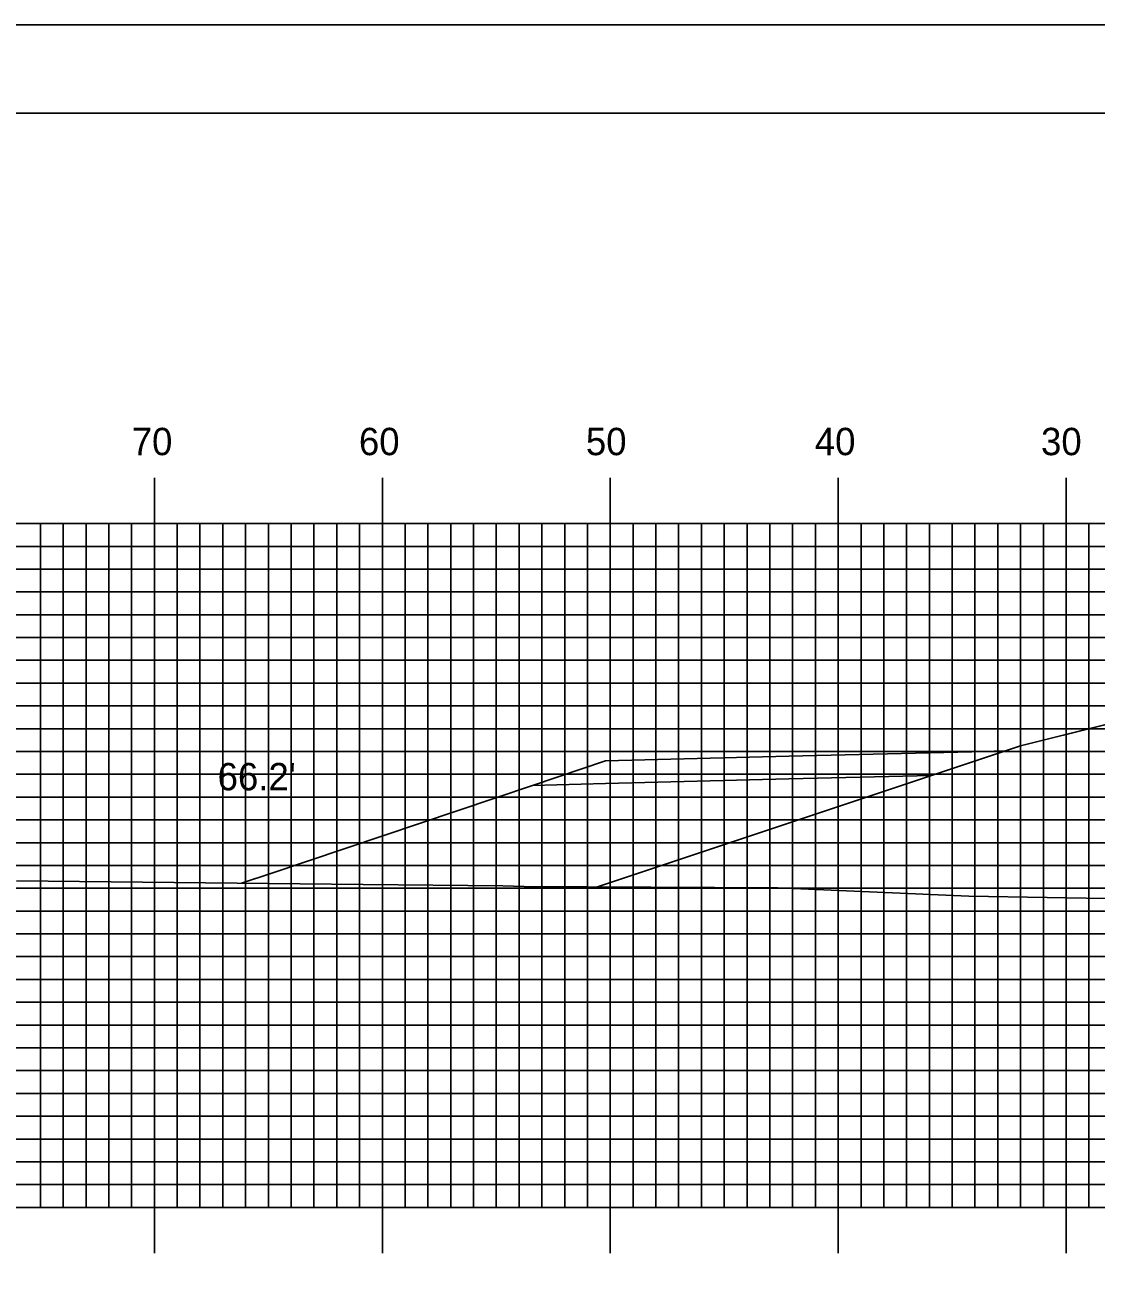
# Model space of a CAD drawing. Extents: x 1807832 to 1808175, y 442591 to 442811.
# Drawn here: x 1807922.1 to 1807969.1, y 442756.2 to 442810.5 of the extents above; entities that cross this region are included whole.
import ezdxf

# ---------------------------------------------------------------- set-up
doc = ezdxf.new("R2010")
doc.units = 0
for name, color, linetype in [('BORDER', 7, 'Continuous'), ('D_Roadway_Centerline', 7, 'Continuous'), ('D_Roadway_Drive_Gravel', 7, 'Continuous'), ('D_Roadway_SlopeLines', 7, 'Continuous'), ('D_Text_Standard', 7, 'Continuous'), ('H_V ANNOTATION', 7, 'Continuous'), ('MAJOR', 7, 'Continuous'), ('MINOR', 7, 'Continuous'), ('PLOT BOUNDARY', 7, 'Continuous'), ('S_Roadway_Centerline', 7, 'Continuous')]:
    doc.layers.add(name, color=color, linetype=linetype)

msp = doc.modelspace()

# ---------------------------------------------------------------- linework, layer by layer
at = {"layer": 'BORDER'}
msp.add_lwpolyline([(1807848.185, 442596.665), (1808168.185, 442596.665), (1808168.185, 442806.665), (1807848.185, 442806.665)], close=True, dxfattribs=at)
at = {"layer": 'D_Roadway_Centerline'}
msp.add_lwpolyline([(1807947.223, 442772.728), (1807965.785, 442778.915), (1807969.423, 442779.824), (1807977.785, 442781.915), (1807985.785, 442782.235), (1807997.785, 442782.475), (1808009.785, 442782.235), (1808017.785, 442781.915), (1808026.147, 442779.824), (1808029.785, 442778.915), (1808057.777, 442769.585)], dxfattribs=at)
at = {"layer": 'D_Roadway_Drive_Gravel'}
msp.add_lwpolyline([(1807963.65, 442778.658), (1807955.612, 442778.459), (1807947.575, 442778.261), (1807944.368, 442777.181), (1807947.575, 442777.261), (1807955.612, 442777.459), (1807961.883, 442777.614)], dxfattribs=at)
at = {"layer": 'D_Roadway_SlopeLines'}
for p, q in [((1807963.65, 442778.658), (1807965.123, 442778.694)), ((1807932.888, 442773.317), (1807931.61, 442772.887))]:
    msp.add_line(p, q, dxfattribs=at)
for points in [[(1807977.785, 442781.915), (1807965.785, 442778.915), (1807947.223, 442772.728)], [(1807947.575, 442778.261), (1807944.368, 442777.181), (1807932.888, 442773.317)]]:
    msp.add_lwpolyline(points, dxfattribs=at)
at = {"layer": 'MAJOR'}
for p, q in [((1807927.785, 442790.669), (1807927.785, 442788.665)), ((1807937.785, 442790.669), (1807937.785, 442788.665)), ((1807947.785, 442790.669), (1807947.785, 442788.665)), ((1807957.785, 442790.669), (1807957.785, 442788.665)), ((1807967.785, 442790.669), (1807967.785, 442788.665)), ((1807857.785, 442788.665), (1808137.785, 442788.665)), ((1807857.785, 442788.665), (1808137.785, 442788.665)), ((1807927.785, 442758.665), (1807927.785, 442788.665)), ((1807937.785, 442758.665), (1807937.785, 442788.665)), ((1807947.785, 442758.665), (1807947.785, 442788.665)), ((1807957.785, 442758.665), (1807957.785, 442788.665)), ((1807967.785, 442758.665), (1807967.785, 442788.665)), ((1807857.785, 442783.665), (1808137.785, 442783.665)), ((1807857.785, 442778.665), (1808137.785, 442778.665)), ((1807857.785, 442773.665), (1808137.785, 442773.665)), ((1807857.785, 442768.665), (1808137.785, 442768.665)), ((1807857.785, 442763.665), (1808137.785, 442763.665)), ((1807857.785, 442758.665), (1808137.785, 442758.665)), ((1807857.785, 442758.665), (1808137.785, 442758.665)), ((1807927.785, 442756.661), (1807927.785, 442758.665)), ((1807937.785, 442756.661), (1807937.785, 442758.665)), ((1807947.785, 442756.661), (1807947.785, 442758.665)), ((1807957.785, 442756.661), (1807957.785, 442758.665)), ((1807967.785, 442756.661), (1807967.785, 442758.665))]:
    msp.add_line(p, q, dxfattribs=at)
at = {"layer": 'MINOR'}
for p, q in [((1807922.785, 442758.665), (1807922.785, 442788.665)), ((1807923.785, 442758.665), (1807923.785, 442788.665)), ((1807924.785, 442758.665), (1807924.785, 442788.665)), ((1807925.785, 442758.665), (1807925.785, 442788.665)), ((1807926.785, 442758.665), (1807926.785, 442788.665)), ((1807928.785, 442758.665), (1807928.785, 442788.665)), ((1807929.785, 442758.665), (1807929.785, 442788.665)), ((1807930.785, 442758.665), (1807930.785, 442788.665)), ((1807931.785, 442758.665), (1807931.785, 442788.665)), ((1807932.785, 442758.665), (1807932.785, 442788.665)), ((1807933.785, 442758.665), (1807933.785, 442788.665)), ((1807934.785, 442758.665), (1807934.785, 442788.665)), ((1807935.785, 442758.665), (1807935.785, 442788.665)), ((1807936.785, 442758.665), (1807936.785, 442788.665)), ((1807938.785, 442758.665), (1807938.785, 442788.665)), ((1807939.785, 442758.665), (1807939.785, 442788.665)), ((1807940.785, 442758.665), (1807940.785, 442788.665)), ((1807941.785, 442758.665), (1807941.785, 442788.665)), ((1807942.785, 442758.665), (1807942.785, 442788.665)), ((1807943.785, 442758.665), (1807943.785, 442788.665)), ((1807944.785, 442758.665), (1807944.785, 442788.665)), ((1807945.785, 442758.665), (1807945.785, 442788.665)), ((1807946.785, 442758.665), (1807946.785, 442788.665)), ((1807948.785, 442758.665), (1807948.785, 442788.665)), ((1807949.785, 442758.665), (1807949.785, 442788.665)), ((1807950.785, 442758.665), (1807950.785, 442788.665)), ((1807951.785, 442758.665), (1807951.785, 442788.665)), ((1807952.785, 442758.665), (1807952.785, 442788.665)), ((1807953.785, 442758.665), (1807953.785, 442788.665)), ((1807954.785, 442758.665), (1807954.785, 442788.665)), ((1807955.785, 442758.665), (1807955.785, 442788.665)), ((1807956.785, 442758.665), (1807956.785, 442788.665)), ((1807958.785, 442758.665), (1807958.785, 442788.665)), ((1807959.785, 442758.665), (1807959.785, 442788.665)), ((1807960.785, 442758.665), (1807960.785, 442788.665)), ((1807961.785, 442758.665), (1807961.785, 442788.665)), ((1807962.785, 442758.665), (1807962.785, 442788.665)), ((1807963.785, 442758.665), (1807963.785, 442788.665)), ((1807964.785, 442758.665), (1807964.785, 442788.665)), ((1807965.785, 442758.665), (1807965.785, 442788.665)), ((1807966.785, 442758.665), (1807966.785, 442788.665)), ((1807968.785, 442758.665), (1807968.785, 442788.665)), ((1807857.785, 442787.665), (1808137.785, 442787.665)), ((1807857.785, 442786.665), (1808137.785, 442786.665)), ((1807857.785, 442785.665), (1808137.785, 442785.665)), ((1807857.785, 442784.665), (1808137.785, 442784.665)), ((1807857.785, 442782.665), (1808137.785, 442782.665)), ((1807857.785, 442781.665), (1808137.785, 442781.665)), ((1807857.785, 442780.665), (1808137.785, 442780.665)), ((1807857.785, 442779.665), (1808137.785, 442779.665)), ((1807857.785, 442777.665), (1808137.785, 442777.665)), ((1807857.785, 442776.665), (1808137.785, 442776.665)), ((1807857.785, 442775.665), (1808137.785, 442775.665)), ((1807857.785, 442774.665), (1808137.785, 442774.665)), ((1807857.785, 442772.665), (1808137.785, 442772.665)), ((1807857.785, 442771.665), (1808137.785, 442771.665)), ((1807857.785, 442770.665), (1808137.785, 442770.665)), ((1807857.785, 442769.665), (1808137.785, 442769.665)), ((1807857.785, 442767.665), (1808137.785, 442767.665)), ((1807857.785, 442766.665), (1808137.785, 442766.665)), ((1807857.785, 442765.665), (1808137.785, 442765.665)), ((1807857.785, 442764.665), (1808137.785, 442764.665)), ((1807857.785, 442762.665), (1808137.785, 442762.665)), ((1807857.785, 442761.665), (1808137.785, 442761.665)), ((1807857.785, 442760.665), (1808137.785, 442760.665)), ((1807857.785, 442759.665), (1808137.785, 442759.665))]:
    msp.add_line(p, q, dxfattribs=at)
at = {"layer": 'PLOT BOUNDARY'}
msp.add_lwpolyline([(1807831.998, 442590.547), (1808171.998, 442590.547), (1808171.998, 442810.547), (1807831.998, 442810.547)], close=True, dxfattribs=at)
at = {"layer": 'S_Roadway_Centerline'}
msp.add_lwpolyline([(1807921.732, 442772.994), (1807936.94, 442772.829), (1807943.067, 442772.776), (1807944.005, 442772.748), (1807955.133, 442772.678), (1807963.517, 442772.314), (1807973.831, 442772.147), (1807985.959, 442772.037), (1807991.535, 442771.851), (1807998.316, 442771.267), (1808002.311, 442770.936), (1808006.301, 442770.888), (1808014.571, 442770.886), (1808023.693, 442770.684), (1808027.77, 442770.528), (1808048.536, 442769.862), (1808050.253, 442769.825), (1808061.117, 442769.478)], dxfattribs=at)

# ---------------------------------------------------------------- texts
at = {"layer": 'D_Text_Standard'}
msp.add_text("66.2'", height=1.2, dxfattribs=at).set_placement((1807930.557, 442776.962))
at = {"layer": 'H_V ANNOTATION'}
for s, p in [('70', (1807926.789, 442791.665)), ('60', (1807936.757, 442791.665)), ('50', (1807946.714, 442791.665)), ('40', (1807956.757, 442791.665)), ('30', (1807966.682, 442791.665))]:
    msp.add_text(s, height=1.2, dxfattribs=at).set_placement(p)

doc.saveas('drawing.dxf')
